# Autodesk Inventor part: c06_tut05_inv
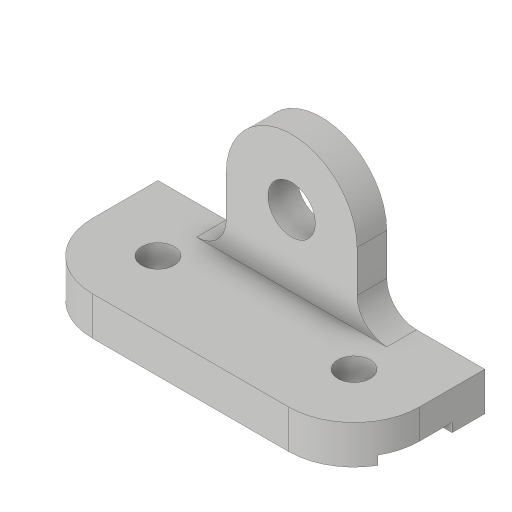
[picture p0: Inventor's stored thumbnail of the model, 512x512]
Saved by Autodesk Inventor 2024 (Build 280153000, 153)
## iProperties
Created: 2015-03
Part Number: c06_tut05_inv
Material: Generic
Document SubType Name: Modeling
Designer: Sandeep
Density: 1 g/cm^3
Appearance: Default
Author: Sandeep
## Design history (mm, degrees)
sketch "Sketch1"
  geometry: L1 (-11, 0)-(11, 0); L2 (11, 0)-(11, -3); L3 (11, -3)-(22, -3); L4 (22, -3)-(22, 10); L5 (22, 10)-(-22, 10); L6 (-22, 10)-(-22, -3); L7 (-22, -3)-(-11, -3); L8 (-11, -3)-(-11, 0); L9 (0, 13.216)-(0, -4.005); 2 further points
  constraints: 18 end point, 6 perpendicular, 4 point on line, 2 midpoint, 1 horizontal, 1 vertical, 1 other
  dimensions: "d0" = 22 distance of L1.start L1.end; "d1" = 44 distance of L4.end L5.end; "d2" = 3 distance between parallel lines of L1 L3; "d3" = 13 distance between parallel lines of L5 L3
extrude "Extrusion1" new body sketch "Sketch1" stored distance "d4" = 110; taper "d5" = 0 deg
fillet "Fillet1" dims "d6" = 22
mirror "Mirror1"
sketch "Sketch2"
  geometry: L1 (22, 0)-(88, 0) reference; L2 (77, 0)-(77, -24); L3 (33, -24)-(33, 0); L4 (77, 0)-(33, 0); L5 (0, 13)-(110, 13) reference; L6 (0, 0)-(0, 13) reference; C1 r 8 at (55, -24); A1 r 22 centre (55, -24) between (33, -24) and (77, -24); 1 further point
  constraints: 6 end point, 2 centre point, 2 point on circle, 2 point on line, 2 tangent, 1 coincident, 1 collinear, 1 parallel, 1 vertical
  dimensions: "d7" = 22 radius of A1; "d8" = 37 distance from line of L5 A1.centre; "d9" = 55 distance from line of L6 A1.centre; "d23" = 16 diameter of C1
extrude "Extrusion2" join sketch "Sketch2" distance "d11" = 10; taper "d12" = 0 deg
fillet "Fillet2" dims "d13" = 10
mirror "Mirror2"
hole "Hole1" diameter "d16" = 11; stored, may be unused: countersink angle "d20" = 90 deg, drill point angle "d22" = 118 deg; dims "d14" = 10, "d15" = 10, "d17" = 6, "d18" = 4, "d19" = 2, "d21" = 8
mirror "Mirror3"
body "Solid1"
